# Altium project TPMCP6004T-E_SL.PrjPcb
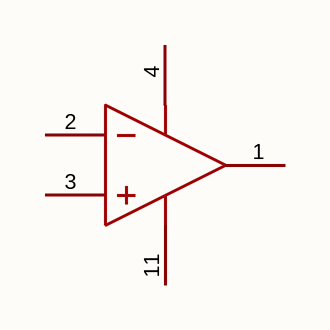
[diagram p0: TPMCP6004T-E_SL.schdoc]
1 sheet, 1 parts. Net scope: global (net labels, ports and power ports of the same name join across sheets).

## Sheet TPMCP6004T-E_SL.schdoc
size 127 x 101 mm

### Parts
U?  tpmcp6004t-e/sl  [SOP-14_L8.7-W3.9-P1.27-LS6.0-BL]  (value not drawn)  (part A of 4)

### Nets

Not connected (* = marked no-connect by the designer): U? 1(1OUT) 2(1IN−) 3(1IN+) 4(V+) 11(V-)

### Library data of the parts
U? = tpmcp6004t-e/sl: 放大器数:2;轨到轨:轨到轨输入,轨到轨输出;增益带宽积(GBW):1MHz;输入失调电压(Vos):5mV;压摆率(SR):-;输入偏置电流(Ib):10pA;; Manufacturer: TECH PUBLIC(台舟); AddInBom: yes; ModelId: 81979219354241bfb99806b876ac1c80; ModelTransform: 342.519,236.22,0,0,0,0,0,0,0; Number of Channels: 2; Gain Bandwidth Product: 1MHz; Vos - Input Offset Voltage: 5mV; Input Offset Voltage Drift(Vos TC): 650nV/℃; Ib - Input Bias Current: 10pA; Common Mode Rejection Ratio(CMRR): 95dB; Quiescent Current: 50uA; Output Current: 20mA; Single supply: 2.1V~5.5V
